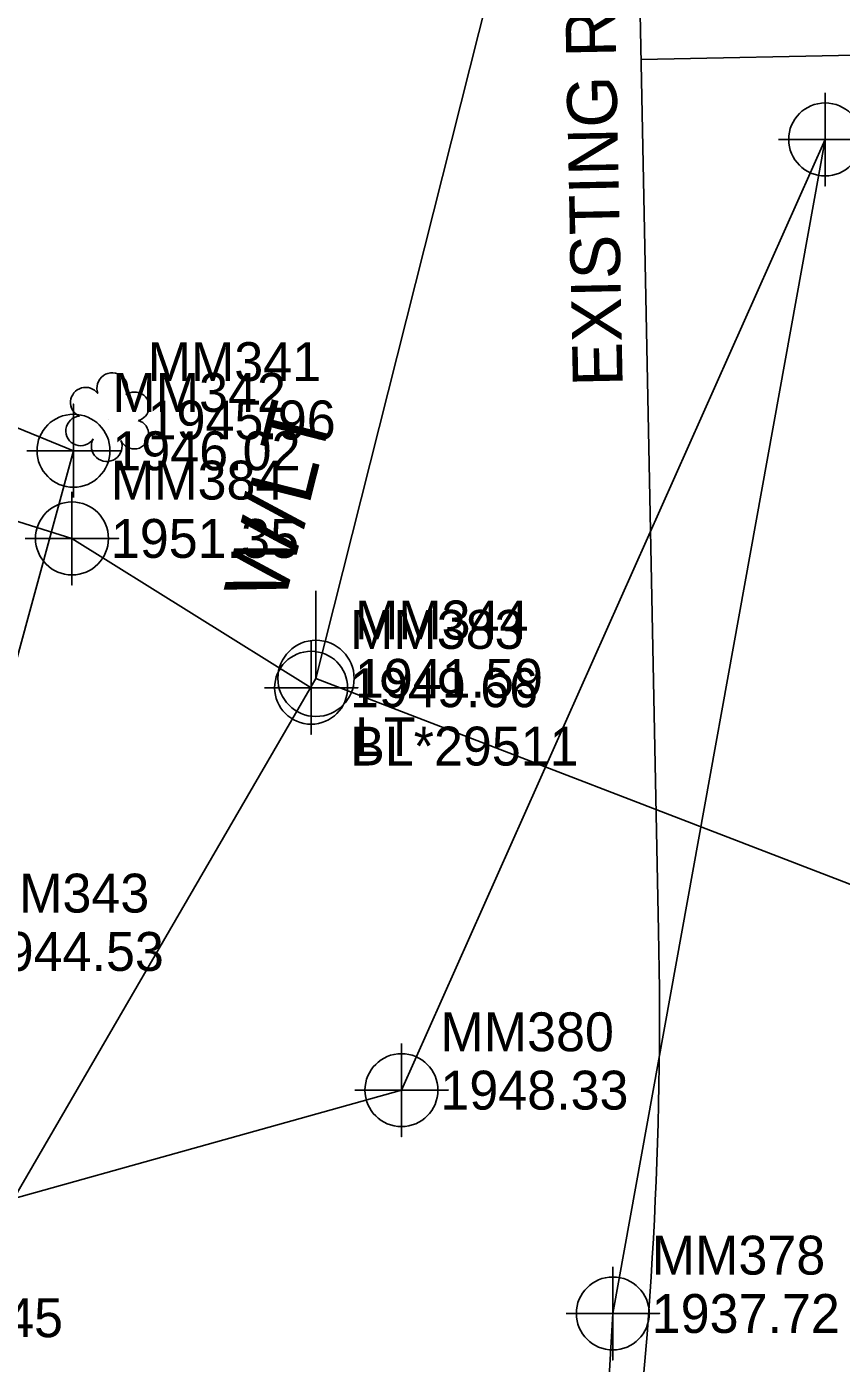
# Model space of a CAD drawing. Extents: x 1004514 to 1005247, y 553695 to 554706.
# Drawn here: x 1004934 to 1004986.4, y 553941.7 to 554027.6 of the extents above; entities that cross this region are included whole.
import ezdxf

# ---------------------------------------------------------------- set-up
doc = ezdxf.new("R2010")
doc.units = 0
for name, color, linetype in [('Exist Right of Way Line', 7, 'Continuous'), ('Exist Right of Way Line Text', 7, 'Continuous'), ('Exist Right of Way Width CELL', 7, 'Continuous'), ('Exist Roads Soil', 7, 'Continuous'), ('Exist Roads Soil Cogo Elevation', 7, 'Continuous'), ('Exist Roads Soil Cogo Number', 7, 'Continuous'), ('Exist Roads Soil Cogo Point CELL', 7, 'Continuous'), ('Exist Utilities Power Pole CELL', 7, 'Continuous'), ('Exist Utilities Power Pole Cogo Comment', 7, 'Continuous'), ('Exist Utilities Power Pole Cogo Elevation', 7, 'Continuous'), ('Exist Utilities Power Pole Cogo Number', 7, 'Continuous'), ('Exist Utilities Power Pole Text', 7, 'Continuous'), ('Exist Utilities Power UG Cable SUE LOS B', 7, 'Continuous'), ('Exist Utilities Power UG Cable SUE LOS B Cogo Comment', 7, 'Continuous'), ('Exist Utilities Power UG Cable SUE LOS B Cogo Elevation', 7, 'Continuous'), ('Exist Utilities Power UG Cable SUE LOS B Cogo Number', 7, 'Continuous'), ('Exist Utilities Power UG Cable SUE LOS B Cogo Point CELL', 7, 'Continuous'), ('Exist Vegetation Shrub CELL', 7, 'Continuous'), ('Exist Vegetation Shrub Cogo Elevation', 7, 'Continuous'), ('Exist Vegetation Shrub Cogo Number', 7, 'Continuous'), ('Exist Vegetation Woods Line', 7, 'Continuous'), ('Exist Vegetation Woods Line Cogo Comment', 7, 'Continuous'), ('Exist Vegetation Woods Line Cogo Elevation', 7, 'Continuous'), ('Exist Vegetation Woods Line Cogo Number', 7, 'Continuous'), ('Exist Vegetation Woods Line Cogo Point CELL', 7, 'Continuous'), ('Scratch_Level_3', 7, 'Continuous')]:
    doc.layers.add(name, color=color, linetype=linetype)

msp = doc.modelspace()

# ---------------------------------------------------------------- linework, layer by layer
at = {"layer": 'Exist Right of Way Line'}
msp.add_line((1004974.633, 553969.453), (1004971.246, 554136.929), dxfattribs=at)
msp.add_arc((1004709.687, 553964.095), 265, 344.07394, 1.15854, dxfattribs=at)
at = {"layer": 'Exist Right of Way Width CELL'}
msp.add_line((1004973.5, 554025.487), (1005014.553, 554026.318), dxfattribs=at)
at = {"layer": 'Exist Roads Soil'}
msp.add_lwpolyline([(1004902.345, 554049.201), (1004911.013, 554044.44), (1004908.227, 554025.602), (1004914.669, 554009.493), (1004937.036, 554000.34), (1004928.257, 553968.154), (1004911.901, 553969.693), (1004894.395, 553961.828)], dxfattribs=at)
at = {"layer": 'Exist Roads Soil Cogo Point CELL'}
msp.add_lwpolyline([(1004937.036, 553997.34), (1004937.036, 554003.34), (1004937.036, 554000.34), (1004940.036, 554000.34), (1004934.036, 554000.34)], dxfattribs=at)
msp.add_circle((1004937.036, 554000.34), 2.344, dxfattribs=at)
at = {"layer": 'Exist Utilities Power Pole CELL'}
for q in [(1004952.616, 553991.336), (1004952.616, 553985.711)]:
    msp.add_line((1004952.616, 553985.711), q, dxfattribs=at)
msp.add_circle((1004952.616, 553985.711), 2.45, dxfattribs=at)
at = {"layer": 'Exist Utilities Power UG Cable SUE LOS B'}
msp.add_lwpolyline([(1004952.305, 553985.107), (1004936.937, 553994.705), (1004908.581, 554003.608)], dxfattribs=at)
at = {"layer": 'Exist Utilities Power UG Cable SUE LOS B Cogo Point CELL'}
for points in [[(1004936.937, 553997.705), (1004936.937, 553991.705), (1004936.937, 553994.705), (1004939.937, 553994.705), (1004933.937, 553994.705)], [(1004952.305, 553988.107), (1004952.305, 553982.107), (1004952.305, 553985.107), (1004955.305, 553985.107), (1004949.305, 553985.107)]]:
    msp.add_lwpolyline(points, dxfattribs=at)
for centre in [(1004936.937, 553994.705), (1004952.305, 553985.107)]:
    msp.add_circle(centre, 2.344, dxfattribs=at)
at = {"layer": 'Exist Vegetation Shrub CELL'}
msp.add_line((1004939.298, 554002.321), (1004939.298, 554002.321), dxfattribs=at)
for centre, radius, start, end in [((1004939.527, 554004.362), 0.99, 334.83907, 200.47174), ((1004937.815, 554003.448), 0.968, 35.89076, 245.42165), ((1004940.97, 554003.19), 0.929, 284.45672, 126.08612), ((1004937.498, 554001.617), 0.955, 95.10992, 327.95341), ((1004940.935, 554001.392), 0.937, 204.99133, 73.46012), ((1004939.17, 554000.638), 0.984, 151.27966, 21.38702)]:
    msp.add_arc(centre, radius, start, end, dxfattribs=at)
at = {"layer": 'Exist Vegetation Woods Line'}
msp.add_lwpolyline([(1004919.176, 553948.358), (1004958.109, 553959.238), (1004985.331, 554020.354), (1004971.688, 553944.88), (1004966.612, 553857.343)], dxfattribs=at)
at = {"layer": 'Exist Vegetation Woods Line Cogo Point CELL'}
for points in [[(1004985.331, 554023.354), (1004985.331, 554017.354), (1004985.331, 554020.354), (1004988.331, 554020.354), (1004982.331, 554020.354)], [(1004958.109, 553962.238), (1004958.109, 553956.238), (1004958.109, 553959.238), (1004961.109, 553959.238), (1004955.109, 553959.238)], [(1004971.688, 553947.88), (1004971.688, 553941.88), (1004971.688, 553944.88), (1004974.688, 553944.88), (1004968.688, 553944.88)]]:
    msp.add_lwpolyline(points, dxfattribs=at)
for centre in [(1004985.331, 554020.354), (1004958.109, 553959.238), (1004971.688, 553944.88)]:
    msp.add_circle(centre, 2.344, dxfattribs=at)
at = {"layer": 'Scratch_Level_3'}
for p, q in [((1004952.616, 553985.711), (1005030.054, 554292.752)), ((1004831.789, 553777.691), (1004952.616, 553985.711)), ((1004952.616, 553985.711), (1005050.606, 553947.91))]:
    msp.add_line(p, q, dxfattribs=at)

# ---------------------------------------------------------------- texts
at = {"layer": 'Exist Right of Way Line Text'}
msp.add_text('EXISTING R/W', height=3.2, rotation=91.15854, dxfattribs=at).set_placement((1004972.324, 554004.502))
at = {"layer": 'Exist Roads Soil Cogo Elevation'}
for s, p in [('1946.02', (1004939.536, 553999.09)), ('1944.53', (1004930.757, 553966.904))]:
    msp.add_text(s, height=2.5, dxfattribs=at).set_placement(p)
at = {"layer": 'Exist Roads Soil Cogo Number'}
for s, p in [('MM342', (1004939.536, 554002.84)), ('MM343', (1004930.757, 553970.654))]:
    msp.add_text(s, height=2.5, dxfattribs=at).set_placement(p)
at = {"layer": 'Exist Utilities Power Pole Cogo Comment'}
msp.add_text('LT', height=2.5, dxfattribs=at).set_placement((1004955.117, 553980.711))
at = {"layer": 'Exist Utilities Power Pole Cogo Elevation'}
msp.add_text('1941.59', height=2.5, dxfattribs=at).set_placement((1004955.117, 553984.461))
at = {"layer": 'Exist Utilities Power Pole Cogo Number'}
msp.add_text('MM344', height=2.5, dxfattribs=at).set_placement((1004955.117, 553988.211))
at = {"layer": 'Exist Utilities Power Pole Text'}
msp.add_text('W/LT', height=4, rotation=75.80426, dxfattribs=at).set_placement((1004950.554, 553990.404))
at = {"layer": 'Exist Utilities Power UG Cable SUE LOS B Cogo Comment'}
msp.add_text('BL*29511', height=2.5, dxfattribs=at).set_placement((1004954.805, 553980.107))
at = {"layer": 'Exist Utilities Power UG Cable SUE LOS B Cogo Elevation'}
for s, p in [('1951.35', (1004939.437, 553993.455)), ('1949.66', (1004954.805, 553983.857))]:
    msp.add_text(s, height=2.5, dxfattribs=at).set_placement(p)
at = {"layer": 'Exist Utilities Power UG Cable SUE LOS B Cogo Number'}
for s, p in [('MM384', (1004939.437, 553997.205)), ('MM383', (1004954.805, 553987.607))]:
    msp.add_text(s, height=2.5, dxfattribs=at).set_placement(p)
at = {"layer": 'Exist Vegetation Shrub Cogo Elevation'}
msp.add_text('1945.96', height=2.5, dxfattribs=at).set_placement((1004941.798, 554001.071))
at = {"layer": 'Exist Vegetation Shrub Cogo Number'}
msp.add_text('MM341', height=2.5, dxfattribs=at).set_placement((1004941.798, 554004.821))
at = {"layer": 'Exist Vegetation Woods Line Cogo Comment'}
msp.add_text('EL*36045', height=2.5, dxfattribs=at).set_placement((1004921.676, 553943.358))
at = {"layer": 'Exist Vegetation Woods Line Cogo Elevation'}
for s, p in [('1948.33', (1004960.609, 553957.988)), ('1937.72', (1004974.188, 553943.63))]:
    msp.add_text(s, height=2.5, dxfattribs=at).set_placement(p)
at = {"layer": 'Exist Vegetation Woods Line Cogo Number'}
for s, p in [('MM380', (1004960.609, 553961.738)), ('MM378', (1004974.188, 553947.38))]:
    msp.add_text(s, height=2.5, dxfattribs=at).set_placement(p)

doc.saveas('drawing.dxf')
